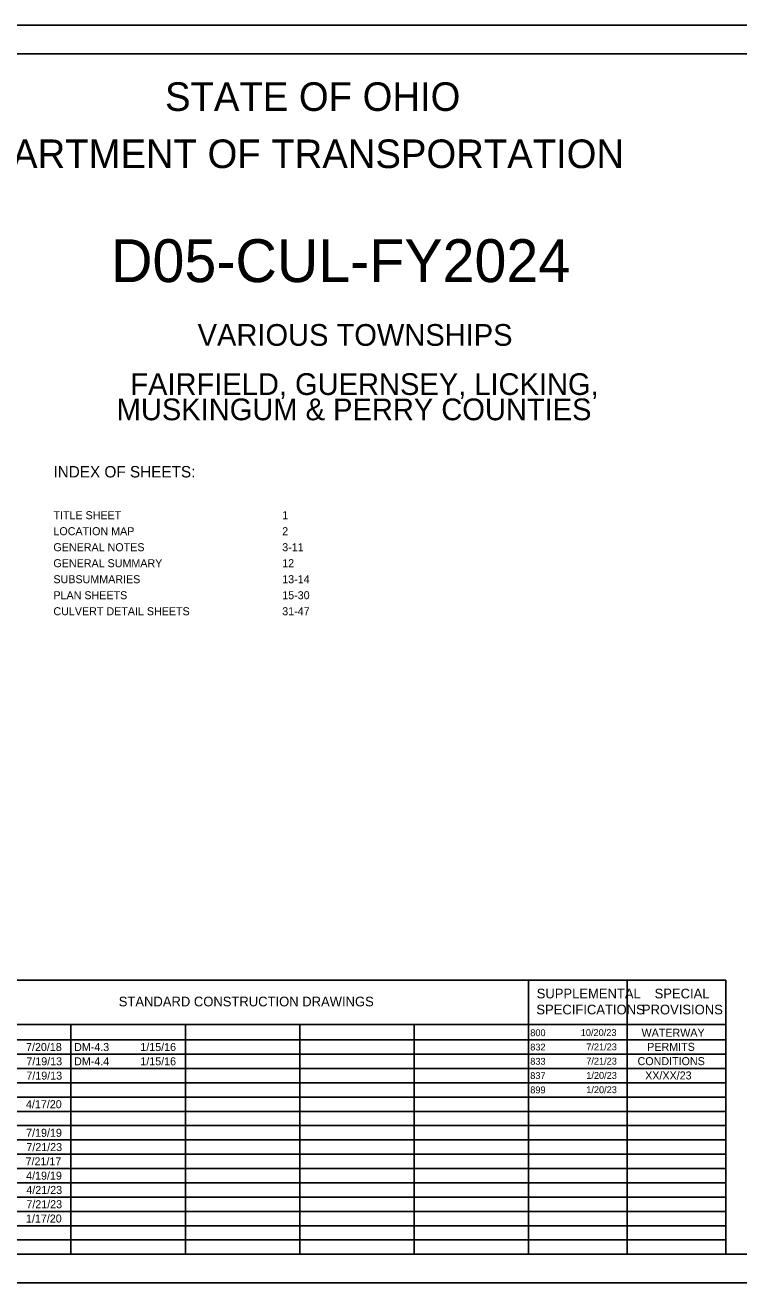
# Model space of a CAD drawing. Extents: x 0 to 34, y 0 to 22.
# Drawn here: x 11.35 to 23.83, y 0 to 22 of the extents above; entities that cross this region are included whole.
import ezdxf

# ---------------------------------------------------------------- set-up
doc = ezdxf.new("R2010")
doc.units = 0
for name, color, linetype in [('SH_Border', 7, 'Continuous'), ('SH_Cut_Line', 7, 'Continuous'), ('SH_Data', 7, 'Continuous'), ('SH_Text', 7, 'Continuous')]:
    doc.layers.add(name, color=color, linetype=linetype)

msp = doc.modelspace()

# ---------------------------------------------------------------- linework, layer by layer
at = {"layer": 'SH_Border'}
msp.add_lwpolyline([(1.5, 21.5), (33.5, 21.5), (33.5, 0.5), (1.5, 0.5)], close=True, dxfattribs=at)
at = {"layer": 'SH_Cut_Line'}
msp.add_lwpolyline([(0, 0), (34, 0), (34, 22), (0, 22)], close=True, dxfattribs=at)
at = {"layer": 'SH_Data'}
for p, q in [((10.15, 5.292), (23.6, 5.292)), ((20.15, 0.5), (20.15, 5.292)), ((21.875, 0.5), (21.875, 5.292)), ((23.6, 0.5), (23.6, 5.292)), ((10.15, 4.521), (23.6, 4.521)), ((12.15, 0.5), (12.15, 4.521)), ((14.15, 0.5), (14.15, 4.521)), ((16.15, 0.5), (16.15, 4.521)), ((18.15, 0.5), (18.15, 4.521)), ((10.15, 4.25), (23.6, 4.25)), ((10.15, 4), (23.6, 4)), ((10.15, 3.75), (23.6, 3.75)), ((10.15, 3.5), (23.6, 3.5)), ((10.15, 3.25), (23.6, 3.25)), ((10.15, 3), (23.6, 3)), ((10.15, 2.75), (23.6, 2.75)), ((10.15, 2.5), (23.6, 2.5)), ((10.15, 2.25), (23.6, 2.25)), ((10.15, 2), (23.6, 2)), ((10.15, 1.75), (23.6, 1.75)), ((10.15, 1.5), (23.6, 1.5)), ((10.15, 1.25), (23.6, 1.25)), ((10.15, 1), (23.6, 1)), ((10.15, 0.75), (23.6, 0.75))]:
    msp.add_line(p, q, dxfattribs=at)

# ---------------------------------------------------------------- texts
at = {"layer": 'SH_Text'}
for s, height, p in [('STATE OF OHIO', 0.5, (13.795, 20.5)), ('DEPARTMENT OF TRANSPORTATION', 0.5, (9.747, 19.5)), ('D05-CUL-FY2024', 0.75, (12.852, 17.505)), ('VARIOUS TOWNSHIPS', 0.38, (14.365, 16.391)), ('FAIRFIELD, GUERNSEY, LICKING,', 0.38, (13.188, 15.531)), ('MUSKINGUM & PERRY COUNTIES', 0.38, (12.95, 15.089)), ('INDEX OF SHEETS:', 0.2, (11.844, 14.088)), ('TITLE SHEET', 0.14, (11.844, 13.358)), ('1', 0.14, (15.844, 13.358)), ('LOCATION MAP', 0.14, (11.844, 13.078)), ('2', 0.14, (15.844, 13.078)), ('GENERAL NOTES', 0.14, (11.844, 12.798)), ('3-11', 0.14, (15.844, 12.798)), ('GENERAL SUMMARY', 0.14, (11.844, 12.518)), ('12', 0.14, (15.844, 12.518)), ('SUBSUMMARIES', 0.14, (11.844, 12.238)), ('13-14', 0.14, (15.844, 12.238)), ('PLAN SHEETS', 0.14, (11.844, 11.958)), ('15-30', 0.14, (15.844, 11.958)), ('CULVERT DETAIL SHEETS', 0.14, (11.844, 11.678)), ('31-47', 0.14, (15.844, 11.678)), ('SUPPLEMENTAL', 0.17, (20.293, 4.976)), ('SPECIAL', 0.17, (22.354, 4.976)), ('STANDARD CONSTRUCTION DRAWINGS', 0.17, (12.986, 4.836)), ('SPECIFICATIONS', 0.17, (20.287, 4.696)), ('PROVISIONS', 0.17, (22.132, 4.696)), ('800', 0.12, (20.18, 4.315)), ('10/20/23', 0.12, (21.063, 4.318)), ('WATERWAY', 0.14, (22.126, 4.305)), ('7/20/18', 0.14, (11.365, 4.055)), ('DM-4.3', 0.14, (12.205, 4.055)), ('1/15/16', 0.14, (13.363, 4.055)), ('832', 0.12, (20.18, 4.065)), ('7/21/23', 0.12, (21.159, 4.068)), ('PERMITS', 0.14, (22.225, 4.058)), ('7/19/13', 0.14, (11.371, 3.805)), ('DM-4.4', 0.14, (12.205, 3.805)), ('1/15/16', 0.14, (13.363, 3.805)), ('833', 0.12, (20.18, 3.815)), ('7/21/23', 0.12, (21.159, 3.818)), ('CONDITIONS', 0.14, (22.056, 3.808)), ('7/19/13', 0.14, (11.371, 3.555)), ('837', 0.12, (20.18, 3.565)), ('1/20/23', 0.12, (21.159, 3.568)), ('XX/XX/23', 0.14, (22.189, 3.558)), ('899', 0.12, (20.18, 3.315)), ('1/20/23', 0.12, (21.159, 3.318)), ('4/17/20', 0.14, (11.364, 3.055)), ('7/19/19', 0.14, (11.367, 2.555)), ('7/21/23', 0.14, (11.371, 2.305)), ('7/21/17', 0.14, (11.357, 2.055)), ('4/19/19', 0.14, (11.367, 1.805)), ('4/21/23', 0.14, (11.371, 1.555)), ('7/21/23', 0.14, (11.371, 1.305)), ('1/17/20', 0.14, (11.364, 1.055))]:
    msp.add_text(s, height=height, dxfattribs=at).set_placement(p)

doc.saveas('drawing.dxf')
